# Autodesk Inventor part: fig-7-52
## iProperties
Shininess: 77.0
Length Units: 11269
Angle Units: 11279
Time Units: 11290
Mass Units: 11283
Length Display Precision: 3
Angle Display Precision: 2
Created: 2002-01
Part Number: fig-7-52
Document SubType Name: Modeling
Designer: ***
Density: 1 g/cm^3
Density: 0.0
Volumn: 0.0
Area: 0.0
PropertySet Name: Model Information
Control State: 0
Master: False
Checked Out: False
Author: ***
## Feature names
1. Extrusion2
2. FaceDraft7
